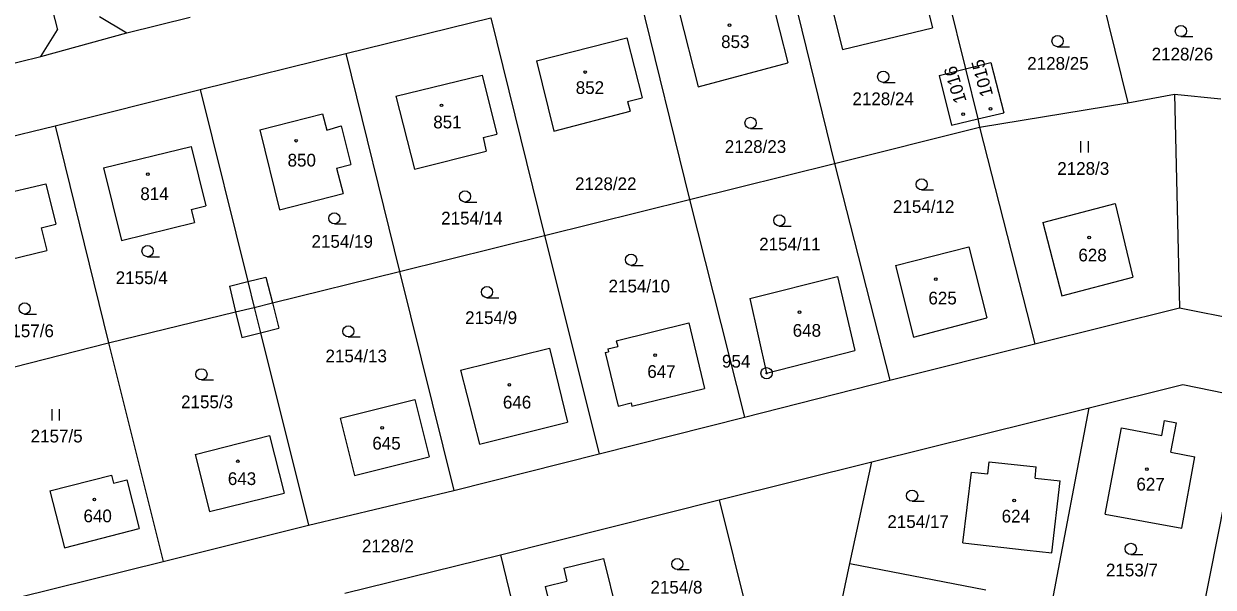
# Model space of a CAD drawing. Extents: x -763205 to -760228, y -1155311 to -1152844.
# Drawn here: x -762213.7 to -762054.7, y -1154656.3 to -1154581 of the extents above; entities that cross this region are included whole.
import ezdxf

# ---------------------------------------------------------------- set-up
doc = ezdxf.new("R2010")
doc.units = 0
for name, color, linetype in [('Vrstva 1', 7, 'Continuous'), ('Vrstva 17', 7, 'Continuous'), ('Vrstva 18', 7, 'Continuous'), ('Vrstva 19', 7, 'Continuous'), ('Vrstva 24', 7, 'Continuous'), ('Vrstva 25', 7, 'Continuous'), ('Vrstva 4', 7, 'Continuous')]:
    doc.layers.add(name, color=color, linetype=linetype)

msp = doc.modelspace()

# ---------------------------------------------------------------- linework, layer by layer
at = {"layer": 'Vrstva 1'}
for p, q in [((-762215.05, -1154558.85), (-762209.19, -1154581.78)), ((-762073.67, -1154560.92), (-762066.09, -1154591.52)), ((-762093.09, -1154565.76), (-762087.78, -1154587)), ((-762112.42, -1154570.56), (-762105.31, -1154599.64)), ((-762094.67, -1154571.61), (-762092.2, -1154581.49)), ((-762106.69, -1154574.61), (-762104.25, -1154584.38)), ((-762131.87, -1154575.35), (-762124.68, -1154604.46)), ((-762114.02, -1154576.39), (-762111.56, -1154586.19)), ((-762126.06, -1154579.4), (-762123.52, -1154589.39)), ((-762203.57, -1154580), (-762199.93, -1154582.19)), ((-762199.93, -1154582.19), (-762191.45, -1154580.08)), ((-762170.67, -1154584.94), (-762151.27, -1154580.15)), ((-762151.27, -1154580.15), (-762144.08, -1154609.25)), ((-762211.43, -1154585.34), (-762209.19, -1154581.78)), ((-762211.43, -1154585.34), (-762199.93, -1154582.19)), ((-762145.17, -1154585.91), (-762133.06, -1154582.84)), ((-762133.06, -1154582.84), (-762131.03, -1154590.87)), ((-762104.25, -1154584.38), (-762092.2, -1154581.49)), ((-762221.13, -1154587.69), (-762211.43, -1154585.34)), ((-762190.11, -1154589.74), (-762170.67, -1154584.94)), ((-762170.67, -1154584.94), (-762163.48, -1154614.06)), ((-762145.17, -1154585.91), (-762142.84, -1154595.33)), ((-762123.52, -1154589.39), (-762111.56, -1154586.19)), ((-762087.78, -1154587), (-762084.39, -1154586.13)), ((-762084.39, -1154586.13), (-762082.69, -1154592.85)), ((-762091.3, -1154587.87), (-762087.78, -1154587)), ((-762087.78, -1154587), (-762086.15, -1154593.65)), ((-762163.95, -1154590.64), (-762152.41, -1154587.82)), ((-762152.41, -1154587.82), (-762150.48, -1154595.73)), ((-762091.3, -1154587.87), (-762089.66, -1154594.49)), ((-762209.51, -1154594.59), (-762190.11, -1154589.74)), ((-762190.11, -1154589.74), (-762183.77, -1154615.42)), ((-762163.95, -1154590.64), (-762161.49, -1154600.41)), ((-762132.98, -1154591.37), (-762131.03, -1154590.87)), ((-762066.09, -1154591.52), (-762059.87, -1154590.35)), ((-762059.87, -1154590.35), (-762053.67, -1154591.01)), ((-762059.87, -1154590.35), (-762059.16, -1154618.91)), ((-762132.98, -1154591.37), (-762132.65, -1154592.66)), ((-762085.94, -1154594.8), (-762066.09, -1154591.52)), ((-762182.17, -1154595.15), (-762173.76, -1154592.98)), ((-762173.76, -1154592.98), (-762173.21, -1154595.2)), ((-762142.84, -1154595.33), (-762132.65, -1154592.66)), ((-762089.66, -1154594.49), (-762086.15, -1154593.65)), ((-762086.15, -1154593.65), (-762082.69, -1154592.85)), ((-762086.15, -1154593.65), (-762085.94, -1154594.8)), ((-762228.9, -1154599.35), (-762209.51, -1154594.59)), ((-762209.51, -1154594.59), (-762202.4, -1154623.62)), ((-762182.17, -1154595.15), (-762179.51, -1154605.84)), ((-762173.21, -1154595.2), (-762171.27, -1154594.59)), ((-762171.27, -1154594.59), (-762169.99, -1154599.77)), ((-762152.31, -1154596.18), (-762150.48, -1154595.73)), ((-762105.31, -1154599.64), (-762085.94, -1154594.8)), ((-762085.94, -1154594.8), (-762078.54, -1154623.76)), ((-762152.31, -1154596.18), (-762151.87, -1154598)), ((-762203.05, -1154600.22), (-762191.33, -1154597.38)), ((-762191.33, -1154597.38), (-762189.39, -1154605.29)), ((-762161.49, -1154600.41), (-762151.87, -1154598)), ((-762203.05, -1154600.22), (-762200.64, -1154609.93)), ((-762171.88, -1154600.28), (-762169.99, -1154599.77)), ((-762171.88, -1154600.28), (-762171.03, -1154603.63)), ((-762124.68, -1154604.46), (-762105.31, -1154599.64)), ((-762105.31, -1154599.64), (-762097.91, -1154628.6)), ((-762223.5, -1154605.28), (-762210.77, -1154602.36)), ((-762210.77, -1154602.36), (-762209.43, -1154607.73)), ((-762179.51, -1154605.84), (-762171.03, -1154603.63)), ((-762144.08, -1154609.25), (-762124.68, -1154604.46)), ((-762124.68, -1154604.46), (-762117.35, -1154633.52)), ((-762077.44, -1154607.53), (-762067.8, -1154604.97)), ((-762067.8, -1154604.97), (-762065.4, -1154614.81)), ((-762191.34, -1154605.78), (-762189.39, -1154605.29)), ((-762191.34, -1154605.78), (-762190.91, -1154607.51)), ((-762211.38, -1154608.22), (-762209.43, -1154607.73)), ((-762211.38, -1154608.22), (-762210.62, -1154611.26)), ((-762200.64, -1154609.93), (-762190.91, -1154607.51)), ((-762077.44, -1154607.53), (-762074.91, -1154617.34)), ((-762163.48, -1154614.06), (-762144.08, -1154609.25)), ((-762144.08, -1154609.25), (-762136.78, -1154638.44)), ((-762221.44, -1154613.86), (-762210.62, -1154611.26)), ((-762097.14, -1154613.27), (-762087.35, -1154610.76)), ((-762087.35, -1154610.76), (-762084.96, -1154620.28)), ((-762180.46, -1154618.26), (-762163.48, -1154614.06)), ((-762163.48, -1154614.06), (-762156.22, -1154643.36)), ((-762116.63, -1154617.66), (-762104.92, -1154614.74)), ((-762104.92, -1154614.74), (-762102.61, -1154624.61)), ((-762097.14, -1154613.27), (-762094.76, -1154622.86)), ((-762074.91, -1154617.34), (-762065.4, -1154614.81)), ((-762183.77, -1154615.42), (-762182.92, -1154618.87)), ((-762116.63, -1154617.66), (-762114.39, -1154627.66)), ((-762202.4, -1154623.62), (-762185.4, -1154619.47)), ((-762185.4, -1154619.47), (-762182.92, -1154618.87)), ((-762182.92, -1154618.87), (-762180.46, -1154618.26)), ((-762182.92, -1154618.87), (-762182.07, -1154622.26)), ((-762078.54, -1154623.76), (-762059.16, -1154618.91)), ((-762059.16, -1154618.91), (-762039.58, -1154622.85)), ((-762134.49, -1154623.35), (-762124.79, -1154620.95)), ((-762124.79, -1154620.95), (-762122.7, -1154629.69)), ((-762094.76, -1154622.86), (-762084.96, -1154620.28)), ((-762182.07, -1154622.26), (-762175.66, -1154647.97)), ((-762221.71, -1154628.5), (-762202.4, -1154623.62)), ((-762202.4, -1154623.62), (-762195.08, -1154652.82)), ((-762155.3, -1154627.26), (-762143.44, -1154624.34)), ((-762143.44, -1154624.34), (-762141.01, -1154634.23)), ((-762135.63, -1154624.42), (-762134.3, -1154624.09)), ((-762134.49, -1154623.35), (-762134.3, -1154624.09)), ((-762097.91, -1154628.6), (-762078.54, -1154623.76)), ((-762135.97, -1154624.91), (-762135.54, -1154624.8)), ((-762135.97, -1154624.91), (-762134.26, -1154632.09)), ((-762135.63, -1154624.42), (-762135.54, -1154624.8)), ((-762114.39, -1154627.66), (-762102.61, -1154624.61)), ((-762155.3, -1154627.26), (-762152.78, -1154637.13)), ((-762117.35, -1154633.52), (-762097.91, -1154628.6)), ((-762132.39, -1154632.06), (-762122.7, -1154629.69)), ((-762071.27, -1154632.31), (-762058.73, -1154629.19)), ((-762058.73, -1154629.19), (-762050.39, -1154630.87)), ((-762171.42, -1154633.66), (-762161.41, -1154631.19)), ((-762161.41, -1154631.19), (-762159.51, -1154638.82)), ((-762134.26, -1154632.09), (-762132.5, -1154631.63)), ((-762132.5, -1154631.63), (-762132.39, -1154632.06)), ((-762100.3, -1154639.53), (-762071.27, -1154632.31)), ((-762076.22, -1154658.3), (-762071.27, -1154632.31)), ((-762056.56, -1154662.09), (-762050.39, -1154630.87)), ((-762171.42, -1154633.66), (-762169.49, -1154641.33)), ((-762136.78, -1154638.44), (-762117.35, -1154633.52)), ((-762152.78, -1154637.13), (-762141.01, -1154634.23)), ((-762069.12, -1154646.52), (-762066.95, -1154634.96)), ((-762066.95, -1154634.96), (-762061.53, -1154635.97)), ((-762061.53, -1154635.97), (-762061.17, -1154633.98)), ((-762061.17, -1154633.98), (-762059.59, -1154634.28)), ((-762060.32, -1154638.23), (-762059.59, -1154634.28)), ((-762190.82, -1154638.55), (-762180.85, -1154636)), ((-762180.85, -1154636), (-762178.9, -1154643.68)), ((-762190.82, -1154638.55), (-762188.88, -1154646.16)), ((-762156.22, -1154643.36), (-762136.78, -1154638.44)), ((-762060.32, -1154638.23), (-762057.13, -1154638.82)), ((-762169.49, -1154641.33), (-762159.51, -1154638.82)), ((-762120.73, -1154644.59), (-762100.3, -1154639.53)), ((-762103.27, -1154653.1), (-762100.3, -1154639.53)), ((-762084.8, -1154641.11), (-762084.62, -1154639.5)), ((-762084.62, -1154639.5), (-762078.33, -1154640.18)), ((-762078.5, -1154641.68), (-762078.33, -1154640.18)), ((-762058.87, -1154648.38), (-762057.13, -1154638.82)), ((-762210.22, -1154643.37), (-762201.97, -1154641.3)), ((-762201.97, -1154641.3), (-762201.7, -1154642.36)), ((-762088.14, -1154650.34), (-762086.98, -1154640.88)), ((-762086.98, -1154640.88), (-762084.8, -1154641.11)), ((-762078.5, -1154641.68), (-762075.14, -1154642.05)), ((-762210.22, -1154643.37), (-762208.29, -1154650.99)), ((-762201.7, -1154642.36), (-762199.95, -1154641.92)), ((-762199.95, -1154641.92), (-762198.28, -1154648.42)), ((-762175.66, -1154647.97), (-762156.22, -1154643.36)), ((-762076.26, -1154651.68), (-762075.14, -1154642.05)), ((-762188.88, -1154646.16), (-762178.9, -1154643.68)), ((-762149.97, -1154651.96), (-762120.73, -1154644.59)), ((-762120.73, -1154644.59), (-762115.91, -1154664.04)), ((-762069.12, -1154646.52), (-762058.87, -1154648.38)), ((-762195.08, -1154652.82), (-762175.66, -1154647.97)), ((-762208.29, -1154650.99), (-762198.28, -1154648.42)), ((-762088.14, -1154650.34), (-762079.57, -1154651.31)), ((-762079.57, -1154651.31), (-762076.26, -1154651.68)), ((-762214.5, -1154657.66), (-762195.08, -1154652.82)), ((-762170.78, -1154657.07), (-762149.97, -1154651.96)), ((-762149.97, -1154651.96), (-762145.19, -1154671.35)), ((-762141.51, -1154653.73), (-762136.2, -1154652.42)), ((-762136.2, -1154652.42), (-762133.87, -1154661.92)), ((-762141.51, -1154653.73), (-762141.09, -1154655.44)), ((-762107.39, -1154672.41), (-762103.27, -1154653.1)), ((-762103.27, -1154653.1), (-762085.07, -1154656.6)), ((-762144.01, -1154656.16), (-762141.09, -1154655.44)), ((-762144.01, -1154656.16), (-762142.09, -1154663.91))]:
    msp.add_line(p, q, dxfattribs=at)
at = {"layer": 'Vrstva 24'}
for radius in [0.75, 0.1]:
    msp.add_circle((-762114.39, -1154627.66), radius, dxfattribs=at)
at = {"layer": 'Vrstva 25'}
for p, q in [((-762058.99, -1154582.68), (-762057.39, -1154582.68)), ((-762075.48, -1154584.03), (-762073.88, -1154584.03)), ((-762098.8, -1154588.79), (-762097.2, -1154588.79)), ((-762116.53, -1154594.96), (-762114.93, -1154594.96)), ((-762072.37, -1154598.17), (-762072.37, -1154596.67)), ((-762071.37, -1154598.17), (-762071.37, -1154596.67)), ((-762093.66, -1154603.17), (-762092.06, -1154603.17)), ((-762154.72, -1154604.79), (-762153.12, -1154604.79)), ((-762172.19, -1154607.71), (-762170.59, -1154607.71)), ((-762112.69, -1154608), (-762111.09, -1154608)), ((-762197.17, -1154612.09), (-762195.57, -1154612.09)), ((-762132.51, -1154613.25), (-762130.91, -1154613.25)), ((-762151.78, -1154617.58), (-762150.18, -1154617.58)), ((-762213.6, -1154619.76), (-762212, -1154619.76)), ((-762170.32, -1154622.82), (-762168.72, -1154622.82)), ((-762189.96, -1154628.56), (-762188.36, -1154628.56)), ((-762209.94, -1154633.97), (-762209.94, -1154632.47)), ((-762208.94, -1154633.97), (-762208.94, -1154632.47)), ((-762094.93, -1154644.78), (-762093.33, -1154644.78)), ((-762065.69, -1154651.89), (-762064.09, -1154651.89)), ((-762126.33, -1154653.92), (-762124.73, -1154653.92))]:
    msp.add_line(p, q, dxfattribs=at)
for centre, radius in [((-762119.34, -1154581.14), 0.175), ((-762058.99, -1154581.93), 0.75), ((-762075.48, -1154583.28), 0.75), ((-762138.65, -1154587.41), 0.175), ((-762098.8, -1154588.04), 0.75), ((-762157.87, -1154591.86), 0.175), ((-762084.45, -1154592.32), 0.175), ((-762116.53, -1154594.21), 0.75), ((-762088.1, -1154593.03), 0.175), ((-762177.31, -1154596.59), 0.175), ((-762197.13, -1154601.07), 0.175), ((-762093.66, -1154602.42), 0.75), ((-762154.72, -1154604.04), 0.75), ((-762172.19, -1154606.96), 0.75), ((-762112.69, -1154607.25), 0.75), ((-762071.27, -1154609.52), 0.175), ((-762197.17, -1154611.34), 0.75), ((-762132.51, -1154612.5), 0.75), ((-762151.78, -1154616.83), 0.75), ((-762091.78, -1154615.09), 0.175), ((-762213.6, -1154619.01), 0.75), ((-762110, -1154619.51), 0.175), ((-762170.32, -1154622.07), 0.75), ((-762129.31, -1154625.26), 0.175), ((-762189.96, -1154627.81), 0.75), ((-762148.79, -1154629.21), 0.175), ((-762165.8, -1154634.96), 0.175), ((-762185.1, -1154639.44), 0.175), ((-762063.53, -1154640.5), 0.175), ((-762094.93, -1154644.03), 0.75), ((-762204.28, -1154644.55), 0.175), ((-762081.29, -1154644.68), 0.175), ((-762065.69, -1154651.14), 0.75), ((-762126.33, -1154653.17), 0.75)]:
    msp.add_circle(centre, radius, dxfattribs=at)
at = {"layer": 'Vrstva 4'}
for p, q in [((-762183.77, -1154615.42), (-762181.34, -1154614.82)), ((-762181.34, -1154614.82), (-762180.46, -1154618.26)), ((-762186.2, -1154616.02), (-762183.77, -1154615.42)), ((-762186.2, -1154616.02), (-762185.4, -1154619.47)), ((-762185.4, -1154619.47), (-762184.57, -1154622.87)), ((-762180.46, -1154618.26), (-762179.62, -1154621.66)), ((-762184.57, -1154622.87), (-762182.07, -1154622.26)), ((-762182.07, -1154622.26), (-762179.62, -1154621.66))]:
    msp.add_line(p, q, dxfattribs=at)

# ---------------------------------------------------------------- texts
at = {"layer": 'Vrstva 17'}
msp.add_text('954', height=1.7, dxfattribs=at).set_placement((-762120.354, -1154626.92))
at = {"layer": 'Vrstva 18'}
for s, p in [('2128/26', (-762062.903, -1154585.86)), ('2128/25', (-762079.543, -1154587.1)), ('2128/24', (-762102.913, -1154591.84)), ('2128/23', (-762119.983, -1154598.22)), ('2128/3', (-762075.523, -1154601.15)), ('2128/22', (-762140.003, -1154603.19)), ('2154/12', (-762097.493, -1154606.24)), ('2154/14', (-762157.903, -1154607.79)), ('2154/19', (-762175.243, -1154610.9)), ('2154/11', (-762115.383, -1154611.26)), ('2155/4', (-762201.423, -1154615.75)), ('2154/10', (-762135.523, -1154616.87)), ('2154/9', (-762154.703, -1154621.09)), ('2157/6', (-762216.643, -1154622.85)), ('2154/13', (-762173.373, -1154626.21)), ('2155/3', (-762192.683, -1154632.34)), ('2157/5', (-762212.803, -1154636.92)), ('2154/17', (-762098.243, -1154648.35)), ('2128/2', (-762168.503, -1154651.6)), ('2153/7', (-762069.013, -1154654.82)), ('2154/8', (-762129.923, -1154657.12))]:
    msp.add_text(s, height=1.7, dxfattribs=at).set_placement(p)
at = {"layer": 'Vrstva 19'}
for s, p in [('853', (-762120.473, -1154584.2)), ('852', (-762139.913, -1154590.34)), ('851', (-762158.963, -1154594.94)), ('850', (-762178.443, -1154600.04)), ('814', (-762198.133, -1154604.52)), ('628', (-762072.703, -1154612.72)), ('625', (-762092.753, -1154618.47)), ('648', (-762110.903, -1154622.79)), ('647', (-762130.343, -1154628.29)), ('646', (-762149.653, -1154632.39)), ('645', (-762167.113, -1154637.87)), ('643', (-762186.433, -1154642.61)), ('627', (-762064.943, -1154643.35)), ('640', (-762205.733, -1154647.59)), ('624', (-762082.963, -1154647.62))]:
    msp.add_text(s, height=1.7, dxfattribs=at).set_placement(p)
for s, rotation, p in [('1015', 105.13776, (-762084.093, -1154590.451)), ('1016', 107.08581, (-762087.625, -1154591.285))]:
    msp.add_text(s, height=1.7, rotation=rotation, dxfattribs=at).set_placement(p)

doc.saveas('drawing.dxf')
